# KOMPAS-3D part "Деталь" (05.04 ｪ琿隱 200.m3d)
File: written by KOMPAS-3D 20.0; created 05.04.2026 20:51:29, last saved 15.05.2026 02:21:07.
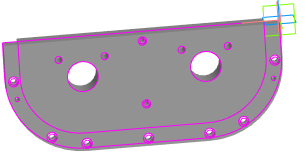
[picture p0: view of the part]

Document properties: Автор: taras; Полное имя файла: E:\test_kompas\all_v18\05.04 крышка200.m3d

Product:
- Part/product: Деталь
    Масса: 19.9484

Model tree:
1. Операция без истории:1
2. Эскиз:3
3. Эскиз:4  (with: Операция без истории:1)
